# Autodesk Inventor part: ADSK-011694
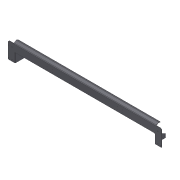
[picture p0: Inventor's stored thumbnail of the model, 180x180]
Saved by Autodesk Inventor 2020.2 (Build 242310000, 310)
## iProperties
Created: 2000-02
Part Number: ADSK-011694
Document SubType Name: Tôlerie
Designer: sspink
Material: Pearson CRS
Density: 1 g/cm^3
Sheet Metal Rule: Stahlblech 1.0312 - DC05 -   5.0 mm
Appearance: Metal-Steel(Polish)
Mass: 2064.83 g
Surface Area: 8565.94 cm^2
Volume: 2064.83 cm^3
Flat Pattern Width: 30.2759 cm
Flat Pattern Length: 217 cm
Flat Pattern Area: 6569.87 cm^2
Sheet Metal Width: 302,759 mm
Sheet Metal Length: 2170,000 mm
Sheet Metal Area: 656987,327 mm^2
Control State: 0
Master: False
Checked Out: False
Shininess: 60.0
Length Units: 11269
Angle Units: 11279
Time Units: 11290
Mass Units: 11283
Length Display Precision: 3
Angle Display Precision: 2
Compacted: True
Cutlength: 704 SI (20.25 X 34.75)
Material Desc: SHEET,HRS,11 GA
Material_Number: Axxxxxx
G_L: 302,8x2170 mm
Thickness: 5,000 mm
Dimensions: 254,9x154,7x2170 mm
Mass: 2,065 kg
Semi finished: Stahlblech 1.0312 - DC05 -   5.0 mm
VLT_Material: 1.0312 DC05
Density: 7.829999999999999
Volumn: 2337.9283514038952
Area: 7761.235605743217
PropertySet Name: Model Information
Author: sspink
Revision Number: -
Title: ADSK-011694
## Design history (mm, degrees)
node "Face1"
  sketch "Sketch1"
    geometry: L1 (-1085, -230)-(-985, -230); L2 (-985, -230)-(-985, 0); L3 (-985, 0)-(-1085, 0); L4 (-1085, 0)-(-1085, -230); L5 (-985, 0)-(985, 0); L6 (985, 0)-(985, -100); L7 (985, -100)-(-985, -100); L8 (-985, -100)-(-985, 0); L9 (985, 0)-(1085, 0); L10 (1085, 0)-(1085, -230); L11 (1085, -230)-(985, -230); L12 (985, -230)-(985, 0); 2 further points
    constraints: 24 end point, 6 parallel, 3 horizontal, 3 perpendicular, 1 coincident, 1 collinear, 1 midpoint
    dimensions: "d0" = 100 distance between parallel lines of L2 L4; "d1" = 100 distance between parallel lines of L10 L12 (derived); "d3" = 230 distance between parallel lines of L3 L1; "d4" = 100 distance between parallel lines of L7 L5; "d5" = 2170 distance between parallel lines of L10 L4
node "Face2"
  sketch "Sketch5"
    geometry: L1 (5, 0)-(150, 0); L2 (150, 0)-(150, 50); L3 (150, 50)-(5, 50); L4 (5, 50)-(5, 0); L5 (150, 50)-(5, 120); L6 (5, 120)-(5, 50); L7 (0, 130)-(0, 0) reference
    constraints: 12 end point, 2 parallel, 2 perpendicular, 1 horizontal
    dimensions: "d16" = 50 distance between parallel lines of L3 L1; "d35" = 70 distance from line of L5.end L3; "d73" = 150 distance between parallel lines of L2 L7
  node "Bend4" dims "d18" = 5 (= BendRadius), "d78" = 5 (derived), "d79" = 2.5 (derived), "d80" = 10 (derived), "d90" = 5 (derived), "SeamGap" = 0.00508, "MinimumRemnant" = 10 (derived), "BendReliefWidth" = 5 (derived)
mirror "Spiegeln2"
workplane "Work Plane1"
node "Lasche6"
node "Hole1" dims "d40" = 4.134, "d41" = 9.525, "d42" = 6.35, "d43" = 60 deg, "d44" = 19.05, "d45" = 118 deg, "d106" = 10
  sketch "Sketch10"
    geometry: L1 (-100, -130)-(-100, 100) reference; L2 (1970, 0)-(0, 0) reference; L3 (450, 58)-(526, 58); L4 (526, 58)-(526, 20); L5 (526, 20)-(450, 20); L6 (450, 20)-(450, 58); 2 further points
    constraints: 8 end point, 2 horizontal alignment, 2 parallel, 2 vertical alignment, 1 horizontal, 1 perpendicular
    dimensions: "d102" = 76 distance of L3.start L3.end; "d103" = 38 distance of L5.end L3.start; "d104" = 20 distance between parallel lines of L2 L5; "d105" = 550 distance between parallel lines of L1 L6
mirror "Spiegeln3"
node "Hole2" dims "d54" = 9, "d55" = 9.525, "d56" = 6.35, "d57" = 60 deg, "d58" = 19.05, "d59" = 118 deg, "d116" = 6
  sketch "Sketch11"
    geometry: L1 (-49.225, 25)-(-11.225, 25); L2 (0.775, 0)-(0.775, 50) reference; L3 (-139.225, 0)-(0.775, 0) reference
    constraints: 2 end point, 1 horizontal
    dimensions: "d107" = 38 distance of L1.start L1.end; "d108" = 12 distance from line of L2 L1.end; "d109" = 25 distance between parallel lines of L3 L1
node "Hole3" dims "d64" = 9, "d65" = 9.525, "d66" = 6.35, "d67" = 60 deg, "d68" = 19.05, "d69" = 118 deg, "d114" = 6
  sketch "Sketch12"
    geometry: L1 (2170, 0)-(2072, 0) reference; L2 (2170, 230)-(2170, 0) reference; L3 (2115, 174.5)-(2161, 174.5); L4 (2161, 174.5)-(2161, 22.5); L5 (2161, 22.5)-(2115, 22.5); L6 (2115, 22.5)-(2115, 174.5); 2 further points
    constraints: 8 end point, 2 coincident, 2 parallel, 1 horizontal, 1 perpendicular
    dimensions: "d110" = 46 distance of L3.start L3.end; "d111" = 152 distance of L3.end L4.end; "d112" = 22.5 distance between parallel lines of L1 L5; "d113" = 9 distance between parallel lines of L2 L4
node "Mirror1"
node "Corner Round1" dims "d71" = 25
node "Corner Round2" dims "d72" = 6
node "Flange5"
  node "Bend8" dims "d74" = 25, "d75" = 60 deg, "d76" = 5 (= BendRadius), "d87" = 5 (derived), "d88" = 2.5 (derived), "d89" = 10 (derived), "d90" = 5 (derived), "d115" = 5 (derived), "SeamGap" = 0.00508
node "Corner Round3" dims "d77" = 12.5
node "Solide1"
node "Corps solides"
node "Corps surfaciques"
node "Plate1" dims "d90" = 5 (derived)
node "Plate5" dims "d18" = 5 (= BendRadius), "d90" = 5 (derived), "MinimumRemnant" = 10 (derived), "BendReliefWidth" = 5 (derived)
sketch "Sketch13"
  geometry: L1 (-2010, 0)-(-2010, -25); L2 (-2010, -25)-(0, -25); 1 other entity
  constraints: 4 end point, 4 other
node "Plate9" dims "d74" = 25, "d75" = 60 deg, "d76" = 5 (= BendRadius), "d87" = 5 (derived), "d88" = 2.5 (derived), "d89" = 10 (derived), "d90" = 5 (derived), "d115" = 5 (derived), "SeamGap" = 0.00508
sketch "Skizze14"
  geometry: L1 (2090, 0)-(80, 0); L2 (80, 0)-(80, -47.113); L3 (80, -47.113)-(2090, -47.113); L4 (2090, -47.113)-(2090, 0)
  constraints: 8 end point
feature "Grobblech10" dims "d90" = 5 (derived), "d91" = 5 (derived), "d92" = 2.5 (derived), "d93" = 10 (derived), "d94" = 5 (derived), "d95" = 2010, "d96" = 50, "d97" = 60 deg, "d98" = 5 (derived), "d99" = 20 (derived), "d100" = 5 (derived), "d101" = 5 (derived), "SeamGap" = 0.00508
feature "Biegung9" dims "d90" = 5 (derived), "d91" = 5 (derived), "d92" = 2.5 (derived), "d93" = 10 (derived), "d94" = 5 (derived), "d96" = 50, "d97" = 60 deg, "d98" = 5 (derived), "SeamGap" = 0.00508
feature "Ecke1" dims "d96" = 50, "d97" = 60 deg, "d99" = 20 (derived), "d100" = 5 (derived), "d101" = 5 (derived)
feature "Definition1"
other parameters: "Thickness" = 5 (derived), "BendRadius" = 5 (derived), "BendReliefDepth" = 2.5 (derived), "d6" = 5 (= BendRadius), "d29" = 150 deg, "TransitionRadius" = 5 (derived), "TailleRayonJacobi" = 5 (derived), "TailleJeu" = 5 (derived), "BendRadius" = 5, "BendReliefDepth" = 2.5, "BendReliefWidth" = 5, "TailleJeu" = 5, "TailleRayonJacobi" = 5, "Thickness" = 5, "TransitionRadius" = 5
